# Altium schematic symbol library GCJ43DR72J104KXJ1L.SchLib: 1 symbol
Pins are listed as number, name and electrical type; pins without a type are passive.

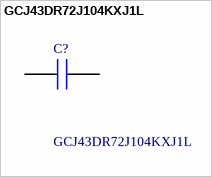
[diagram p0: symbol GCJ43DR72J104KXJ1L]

## GCJ43DR72J104KXJ1L
designator C?
Capacitor GCJ43 L=4.5mm W=3.2mm T=2.0mm; Manufacturer_Name: Murata Electronics; Geometry.Height: 2mm
footprint CAPC4532X200N
pins: 1, 2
